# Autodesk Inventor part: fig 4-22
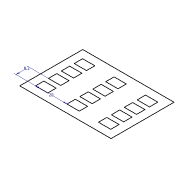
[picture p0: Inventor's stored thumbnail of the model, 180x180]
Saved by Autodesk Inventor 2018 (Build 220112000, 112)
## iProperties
Created: 2004-05
Part Number: fig 4-22
Document SubType Name: Modeling
Designer: CADCIM Technologies
Manufacturer: Standard
Standards Organization: Custom
Density: 1 g/cm^3
Material: Generic
Appearance: Default
Author: CADCIM Technologies
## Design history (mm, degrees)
sketch "Sketch1"
  geometry: L1 (7.752, 6.176)-(65.752, 6.176); L2 (65.752, 6.176)-(65.752, 46.176); L3 (65.752, 46.176)-(7.752, 46.176); L4 (7.752, 46.176)-(7.752, 6.176); L5 (12.752, 11.176)-(20.543, 11.176); L6 (20.543, 11.176)-(20.543, 16.473); L7 (20.543, 16.473)-(12.752, 16.473); L8 (12.752, 16.473)-(12.752, 11.176); L9 (32.752, 11.176)-(40.543, 11.176); L10 (40.543, 11.176)-(40.543, 16.473); L11 (40.543, 16.473)-(32.752, 16.473); L12 (32.752, 16.473)-(32.752, 11.176); L13 (52.752, 11.176)-(60.543, 11.176); L14 (60.543, 11.176)-(60.543, 16.473); L15 (60.543, 16.473)-(52.752, 16.473); L16 (52.752, 16.473)-(52.752, 11.176); L17 (12.752, 19.376)-(20.543, 19.376); L18 (20.543, 19.376)-(20.543, 24.673); L19 (20.543, 24.673)-(12.752, 24.673); L20 (12.752, 24.673)-(12.752, 19.376); L21 (32.752, 19.376)-(40.543, 19.376); L22 (40.543, 19.376)-(40.543, 24.673); L23 (40.543, 24.673)-(32.752, 24.673); L24 (32.752, 24.673)-(32.752, 19.376); L25 (52.752, 19.376)-(60.543, 19.376); L26 (60.543, 19.376)-(60.543, 24.673); L27 (60.543, 24.673)-(52.752, 24.673); L28 (52.752, 24.673)-(52.752, 19.376); L29 (12.752, 27.576)-(20.543, 27.576); L30 (20.543, 27.576)-(20.543, 32.873); L31 (20.543, 32.873)-(12.752, 32.873); L32 (12.752, 32.873)-(12.752, 27.576); L33 (32.752, 27.576)-(40.543, 27.576); L34 (40.543, 27.576)-(40.543, 32.873); L35 (40.543, 32.873)-(32.752, 32.873); L36 (32.752, 32.873)-(32.752, 27.576); L37 (52.752, 27.576)-(60.543, 27.576); L38 (60.543, 27.576)-(60.543, 32.873); L39 (60.543, 32.873)-(52.752, 32.873); L40 (52.752, 32.873)-(52.752, 27.576); L41 (12.752, 35.776)-(20.543, 35.776); L42 (20.543, 35.776)-(20.543, 41.073); L43 (20.543, 41.073)-(12.752, 41.073); L44 (12.752, 41.073)-(12.752, 35.776); L45 (32.752, 35.776)-(40.543, 35.776); L46 (40.543, 35.776)-(40.543, 41.073); L47 (40.543, 41.073)-(32.752, 41.073); L48 (32.752, 41.073)-(32.752, 35.776); L49 (52.752, 35.776)-(60.543, 35.776); L50 (60.543, 35.776)-(60.543, 41.073); L51 (60.543, 41.073)-(52.752, 41.073); L52 (52.752, 41.073)-(52.752, 35.776)
  constraints: 104 end point, 4 parallel, 3 horizontal, 2 perpendicular, 1 vertical, 88 other
  dimensions: "d14" = 20 distance of L5.start L9.start; "d17" = 8.2 distance of L5.start L17.start
